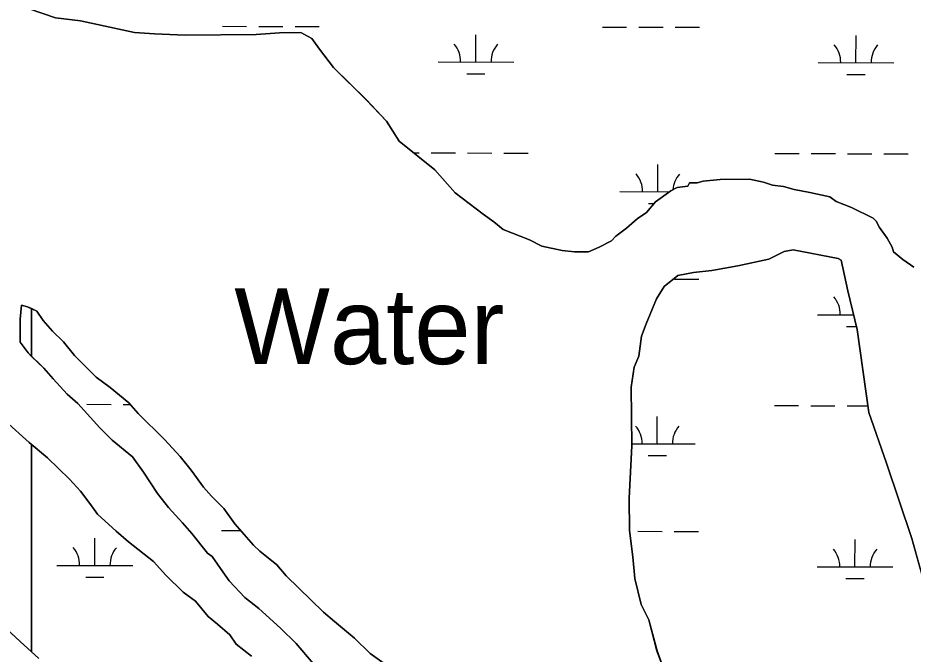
# Model space of a CAD drawing. Extents: x 3192952 to 3230831, y 849296 to 874698.
# Drawn here: x 3214925 to 3216108, y 863705 to 864544 of the extents above; entities that cross this region are included whole.
import ezdxf

# ---------------------------------------------------------------- set-up
doc = ezdxf.new("R2010")
doc.units = 0
for name, color, linetype in [('V-RIVR-IDEN', 7, 'Continuous'), ('V-SITE-VEGE', 7, 'Continuous'), ('V-TOPO-SHOR', 7, 'Continuous'), ('V-WETL-SWMP', 7, 'Continuous')]:
    doc.layers.add(name, color=color, linetype=linetype)

msp = doc.modelspace()

# ---------------------------------------------------------------- linework, layer by layer
at = {"layer": 'V-SITE-VEGE'}
for p, q in [((3214940.5, 864556), (3214975.3, 864544.2)), ((3214975.3, 864544.2), (3215007.9, 864540.4)), ((3215007.9, 864540.4), (3215079.3, 864524.8)), ((3215079.3, 864524.8), (3215105.8, 864523.1)), ((3215105.8, 864523.1), (3215146.5, 864521.4)), ((3215146.5, 864521.4), (3215240.1, 864522.3)), ((3215240.1, 864522.3), (3215270.7, 864524.7)), ((3215270.7, 864524.7), (3215299.2, 864525)), ((3215299.2, 864525), (3215313.5, 864517)), ((3215313.5, 864517), (3215323.8, 864502.8)), ((3215323.8, 864502.8), (3215342.4, 864478.6)), ((3215342.4, 864478.6), (3215385.5, 864436.2)), ((3215385.5, 864436.2), (3215412.3, 864408)), ((3215412.3, 864408), (3215428.8, 864381.7)), ((3215428.8, 864381.7), (3215476, 864343.5)), ((3215476, 864343.5), (3215502.8, 864313.2)), ((3215810.1, 864322.3), (3215812.1, 864326.4)), ((3215812.1, 864326.4), (3215822.3, 864326.5)), ((3215822.3, 864326.5), (3215830.4, 864328.6)), ((3215830.4, 864328.6), (3215852.8, 864330.9)), ((3215852.8, 864330.9), (3215891.5, 864331.3)), ((3215891.5, 864331.3), (3215909.8, 864327.4)), ((3215909.8, 864327.4), (3215922.1, 864323.4)), ((3215767.6, 864301.6), (3215787.8, 864316)), ((3215787.8, 864316), (3215795.9, 864320.2)), ((3215795.9, 864320.2), (3215810.1, 864322.3)), ((3215922.1, 864323.4), (3215936.4, 864321.5)), ((3215936.4, 864321.5), (3215950.7, 864317.6)), ((3215950.7, 864317.6), (3215971.1, 864313.7)), ((3215971.1, 864313.7), (3215997.6, 864307.9)), ((3215502.8, 864313.2), (3215539.7, 864285.1)), ((3215997.6, 864307.9), (3216005.8, 864301.9)), ((3215755.5, 864287.2), (3215767.6, 864301.6)), ((3216005.8, 864301.9), (3216026.2, 864293.9)), ((3216026.2, 864293.9), (3216054.9, 864280)), ((3215539.7, 864285.1), (3215554.1, 864275)), ((3215729.2, 864266.6), (3215743.4, 864278.9)), ((3215743.4, 864278.9), (3215755.5, 864287.2)), ((3216054.9, 864280), (3216059, 864275.9)), ((3215554.1, 864275), (3215566.4, 864265)), ((3215715.1, 864256.3), (3215729.2, 864266.6)), ((3216059, 864275.9), (3216063.1, 864267.8)), ((3216063.1, 864267.8), (3216073.4, 864253.7)), ((3215566.4, 864265), (3215601.1, 864251.1)), ((3215709.1, 864250.1), (3215715.1, 864256.3)), ((3215601.1, 864251.1), (3215617.5, 864243.1)), ((3215617.5, 864243.1), (3215644, 864237.2)), ((3215692.8, 864241.8), (3215709.1, 864250.1)), ((3216073.4, 864253.7), (3216079.7, 864241.5)), ((3215644, 864237.2), (3215660.3, 864235.4)), ((3215660.3, 864235.4), (3215678.7, 864235.5)), ((3215678.7, 864235.5), (3215692.8, 864241.8)), ((3215937.2, 864236), (3215917, 864225.7)), ((3215949.4, 864238.2), (3215937.2, 864236)), ((3216008.6, 864226.6), (3215949.4, 864238.2)), ((3216079.7, 864241.5), (3216081.8, 864235.4)), ((3216081.8, 864235.4), (3216094.1, 864225.4)), ((3215917, 864225.7), (3215876.3, 864217.1)), ((3216012.7, 864224.6), (3216008.6, 864226.6)), ((3216021.2, 864183.9), (3216012.7, 864224.6)), ((3216094.1, 864225.4), (3216108.4, 864215.3)), ((3215817.4, 864208.4), (3215797, 864204.1)), ((3215841.8, 864210.7), (3215817.4, 864208.4)), ((3215876.3, 864217.1), (3215841.8, 864210.7)), ((3215797, 864204.1), (3215778.9, 864189.7)), ((3215778.9, 864189.7), (3215768.8, 864173.3)), ((3216033.9, 864133.2), (3216021.2, 864183.9)), ((3215768.8, 864173.3), (3215754.9, 864140.6)), ((3215754.9, 864140.6), (3215749, 864124.3)), ((3216049.2, 864023.4), (3216033.9, 864133.2)), ((3215749, 864124.3), (3215745.2, 864097.7)), ((3215745.2, 864097.7), (3215739.2, 864083.4)), ((3215739.2, 864083.4), (3215735.4, 864056.9)), ((3215735.4, 864056.9), (3215736.1, 863979.6)), ((3216072.3, 863956.4), (3216049.2, 864023.4)), ((3215736.1, 863979.6), (3215732.8, 863910.3)), ((3216105.9, 863857), (3216072.3, 863956.4)), ((3215732.8, 863910.3), (3215733.2, 863867.6)), ((3215733.2, 863867.6), (3215737.6, 863833)), ((3216146, 863712.8), (3216105.9, 863857)), ((3215737.6, 863833), (3215739.9, 863804.5)), ((3215739.9, 863804.5), (3215748.4, 863770)), ((3215748.4, 863770), (3215758.8, 863749.7)), ((3215758.8, 863749.7), (3215769.3, 863709.1)), ((3215769.3, 863709.1), (3215781.9, 863674.6))]:
    msp.add_line(p, q, dxfattribs=at)
for points in [[(3215421.5, 863683.3), (3215390.7, 863705.4), (3215370.1, 863725.6), (3215343.5, 863747.7), (3215329.1, 863759.8), (3215279.8, 863808.1), (3215267.4, 863822.3), (3215244.8, 863840.4), (3215236.6, 863848.4), (3215211.9, 863876.7), (3215197.4, 863896.9), (3215181, 863913), (3215170.7, 863925.1), (3215154.2, 863947.4), (3215139.8, 863965.6), (3215119.2, 863987.7), (3215084.2, 864022), (3215071.9, 864036.1), (3215047.3, 864056.3), (3215028.8, 864070.3), (3215000, 864098.5), (3214985.6, 864116.7), (3214971.2, 864130.8), (3214958.8, 864145), (3214950.6, 864157.1), (3214938.3, 864163.1), (3214930.1, 864165), (3214928.3, 864146.7), (3214928.6, 864116.2), (3214938.9, 864102), (3214959.5, 864081.9), (3214971.8, 864067.7), (3214990.3, 864047.6), (3215004.7, 864035.5), (3215033.5, 864003.2), (3215050, 863987.1), (3215076.7, 863964.9)], [(3215234, 863701.8), (3215213.5, 863717.9), (3215205.2, 863730), (3215188.8, 863744.1), (3215176.5, 863754.2), (3215160, 863774.4), (3215143.6, 863786.4), (3215120.9, 863808.6), (3215104.5, 863826.8), (3215071.6, 863852.9), (3215055.2, 863867), (3215030.6, 863889.2), (3215020.3, 863903.3), (3215007.9, 863919.5), (3214993.5, 863935.6), (3214964.7, 863963.8), (3214940.1, 863983.9), (3214909.2, 864012.1)], [(3215076.7, 863964.9), (3215091.1, 863944.7), (3215109.7, 863916.4), (3215124.1, 863898.2), (3215142.7, 863878), (3215155, 863863.9), (3215175.6, 863837.6), (3215181.8, 863833.6), (3215196.2, 863813.4), (3215204.5, 863801.3), (3215225.1, 863779.1), (3215243.5, 863765), (3215272.3, 863738.8), (3215292.8, 863718.7), (3215315.5, 863692.4)], [(3214897.6, 863749.4), (3214928.4, 863721.2), (3214953, 863699)]]:
    msp.add_lwpolyline(points, dxfattribs=at)
at = {"layer": 'V-TOPO-SHOR'}
for points in [[(3216108.4, 864215.3), (3216094.1, 864225.4), (3216081.8, 864235.4), (3216079.7, 864241.5), (3216073.4, 864253.7), (3216063.1, 864267.8), (3216059, 864275.9), (3216054.9, 864280), (3216026.2, 864293.9), (3216005.8, 864301.9), (3215997.6, 864307.9), (3215971.1, 864313.7), (3215950.7, 864317.6), (3215936.4, 864321.5), (3215922.1, 864323.4), (3215909.8, 864327.4), (3215891.5, 864331.3), (3215852.8, 864330.9), (3215830.4, 864328.6), (3215822.3, 864326.5), (3215812.1, 864326.4), (3215810.1, 864322.3), (3215795.9, 864320.2), (3215787.8, 864316), (3215767.6, 864301.6), (3215755.5, 864287.2), (3215743.4, 864278.9), (3215729.2, 864266.6), (3215715.1, 864256.3), (3215709.1, 864250.1), (3215692.8, 864241.8), (3215678.7, 864235.5), (3215660.3, 864235.4), (3215644, 864237.2), (3215617.5, 864243.1), (3215601.1, 864251.1), (3215566.4, 864265), (3215554.1, 864275), (3215539.7, 864285.1), (3215502.8, 864313.2), (3215476, 864343.5), (3215428.8, 864381.7), (3215412.3, 864408), (3215385.5, 864436.2), (3215342.4, 864478.6), (3215323.8, 864502.8), (3215313.5, 864517), (3215299.2, 864525), (3215270.7, 864524.7), (3215240.1, 864522.3), (3215146.5, 864521.4), (3215105.8, 864523.1), (3215079.3, 864524.8), (3215007.9, 864540.4), (3214975.3, 864544.2), (3214940.5, 864556)], [(3215781.9, 863674.6), (3215769.3, 863709.1), (3215758.8, 863749.7), (3215748.4, 863770), (3215739.9, 863804.5), (3215737.6, 863833), (3215733.2, 863867.6), (3215732.8, 863910.3), (3215736.1, 863979.6), (3215735.4, 864056.9), (3215739.2, 864083.4), (3215745.2, 864097.7), (3215749, 864124.3), (3215754.9, 864140.6), (3215768.8, 864173.3), (3215778.9, 864189.7), (3215797, 864204.1), (3215817.4, 864208.4), (3215841.8, 864210.7), (3215876.3, 864217.1), (3215917, 864225.7), (3215937.2, 864236), (3215949.4, 864238.2), (3216008.6, 864226.6), (3216012.7, 864224.6), (3216021.2, 864183.9), (3216033.9, 864133.2), (3216049.2, 864023.4), (3216072.3, 863956.4), (3216105.9, 863857), (3216146, 863712.8)], [(3215315.5, 863692.4), (3215292.8, 863718.7), (3215272.3, 863738.8), (3215243.5, 863765), (3215225.1, 863779.1), (3215204.5, 863801.3), (3215196.2, 863813.4), (3215181.8, 863833.6), (3215175.6, 863837.6), (3215155, 863863.9), (3215142.7, 863878), (3215124.1, 863898.2), (3215109.7, 863916.4), (3215091.1, 863944.7), (3215076.7, 863964.9), (3215050, 863987.1), (3215033.5, 864003.2), (3215004.7, 864035.5), (3214990.3, 864047.6), (3214971.8, 864067.7), (3214959.5, 864081.9), (3214938.9, 864102), (3214928.6, 864116.2), (3214928.3, 864146.7), (3214930.1, 864165), (3214938.3, 864163.1), (3214950.6, 864157.1), (3214958.8, 864145), (3214971.2, 864130.8), (3214985.6, 864116.7), (3215000, 864098.5), (3215028.8, 864070.3), (3215047.3, 864056.3), (3215071.9, 864036.1), (3215084.2, 864022), (3215119.2, 863987.7), (3215139.8, 863965.6), (3215154.2, 863947.4), (3215170.7, 863925.1), (3215181, 863913), (3215197.4, 863896.9), (3215211.9, 863876.7), (3215236.6, 863848.4), (3215244.8, 863840.4), (3215267.4, 863822.3), (3215279.8, 863808.1), (3215329.1, 863759.8), (3215343.5, 863747.7), (3215370.1, 863725.6), (3215390.7, 863705.4), (3215421.5, 863683.3)], [(3214909.2, 864012.1), (3214940.1, 863983.9), (3214964.7, 863963.8), (3214993.5, 863935.6), (3215007.9, 863919.5), (3215020.3, 863903.3), (3215030.6, 863889.2), (3215055.2, 863867), (3215071.6, 863852.9), (3215104.5, 863826.8), (3215120.9, 863808.6), (3215143.6, 863786.4), (3215160, 863774.4), (3215176.5, 863754.2), (3215188.8, 863744.1), (3215205.2, 863730), (3215213.5, 863717.9), (3215234, 863701.8)], [(3214953, 863699), (3214928.4, 863721.2), (3214897.6, 863749.4)]]:
    msp.add_lwpolyline(points, dxfattribs=at)
at = {"layer": 'V-WETL-SWMP'}
for p, q in [((3214975.3, 864544.2), (3215007.9, 864540.4)), ((3215007.9, 864540.4), (3215079.3, 864524.8)), ((3215195.4, 864533.1), (3215227.4, 864533)), ((3215243.4, 864533), (3215275.4, 864532.9)), ((3215291.4, 864532.9), (3215323.4, 864532.8)), ((3215697.3, 864532.1), (3215729.3, 864532.1)), ((3215745.3, 864532.1), (3215777.3, 864532)), ((3215793.3, 864532), (3215825.3, 864531.9)), ((3215079.3, 864524.8), (3215105.8, 864523.1)), ((3215105.8, 864523.1), (3215146.5, 864521.4)), ((3215146.5, 864521.4), (3215240.2, 864522.4)), ((3215240.2, 864522.4), (3215270.7, 864524.7)), ((3215270.7, 864524.7), (3215299.2, 864525)), ((3215299.2, 864525), (3215313.5, 864517)), ((3215313.5, 864517), (3215323.8, 864502.8)), ((3215530.2, 864486), (3215530.2, 864522)), ((3216032.1, 864485.1), (3216032.2, 864521.1)), ((3215323.8, 864502.8), (3215342.4, 864478.6)), ((3215480.2, 864486.1), (3215580.2, 864485.9)), ((3215982.1, 864485.2), (3216082.1, 864485)), ((3215342.4, 864478.6), (3215385.6, 864436.2)), ((3215518.1, 864470.6), (3215542.1, 864470.6)), ((3216020.1, 864469.7), (3216044.1, 864469.6)), ((3215385.6, 864436.2), (3215412.3, 864408)), ((3215412.3, 864408), (3215428.8, 864381.7)), ((3215428.8, 864381.7), (3215476, 864343.5)), ((3215448.1, 864366.1), (3215455.1, 864366.1)), ((3215471.1, 864366.1), (3215503.1, 864366)), ((3215519.1, 864366), (3215551.1, 864365.9)), ((3215567.1, 864365.9), (3215599.1, 864365.8)), ((3215925, 864365.2), (3215957, 864365.1)), ((3215973, 864365.1), (3216005, 864365.1)), ((3216021, 864365), (3216053, 864365)), ((3216069, 864364.9), (3216101, 864364.9)), ((3215770.3, 864314.8), (3215770.4, 864350.8)), ((3215476, 864343.5), (3215502.8, 864313.2)), ((3215810.1, 864322.3), (3215812.1, 864326.4)), ((3215812.1, 864326.4), (3215822.3, 864326.5)), ((3215822.3, 864326.5), (3215830.4, 864328.6)), ((3215830.4, 864328.6), (3215852.8, 864330.9)), ((3215852.8, 864330.9), (3215891.5, 864331.3)), ((3215891.5, 864331.3), (3215909.9, 864327.4)), ((3215909.9, 864327.4), (3215922.1, 864323.4)), ((3215720.3, 864314.9), (3215786, 864314.7)), ((3215767.6, 864301.6), (3215787.8, 864316)), ((3215787.8, 864316), (3215795.9, 864320.2)), ((3215795.9, 864320.2), (3215810.1, 864322.3)), ((3215922.1, 864323.4), (3215936.4, 864321.5)), ((3215936.4, 864321.5), (3215950.7, 864317.6)), ((3215950.7, 864317.6), (3215971.1, 864313.7)), ((3215971.1, 864313.7), (3215997.6, 864307.9)), ((3215502.8, 864313.2), (3215539.7, 864285.1)), ((3215997.6, 864307.9), (3216005.8, 864301.9)), ((3215755.5, 864287.2), (3215767.6, 864301.6)), ((3215758.3, 864299.4), (3215765.7, 864299.3)), ((3216005.8, 864301.9), (3216026.2, 864293.9)), ((3216026.2, 864293.9), (3216054.9, 864280)), ((3215539.7, 864285.1), (3215554.1, 864275)), ((3215729.3, 864266.6), (3215743.4, 864278.9)), ((3215743.4, 864278.9), (3215755.5, 864287.2)), ((3216054.9, 864280), (3216059, 864275.9)), ((3215554.1, 864275), (3215566.4, 864265)), ((3215715.1, 864256.3), (3215729.3, 864266.6)), ((3216059, 864275.9), (3216063.1, 864267.8)), ((3216063.1, 864267.8), (3216073.5, 864253.7)), ((3215566.4, 864265), (3215601.1, 864251.1)), ((3215709.1, 864250.1), (3215715.1, 864256.3)), ((3215601.1, 864251.1), (3215617.5, 864243.1)), ((3215617.5, 864243.1), (3215644, 864237.2)), ((3215692.9, 864241.8), (3215709.1, 864250.1)), ((3216073.5, 864253.7), (3216079.7, 864241.5)), ((3215644, 864237.2), (3215660.3, 864235.4)), ((3215660.3, 864235.4), (3215678.7, 864235.5)), ((3215678.7, 864235.5), (3215692.9, 864241.8)), ((3215937.2, 864236), (3215917, 864225.7)), ((3215949.4, 864238.2), (3215937.2, 864236)), ((3216008.6, 864226.6), (3215949.4, 864238.2)), ((3216079.7, 864241.5), (3216081.8, 864235.4)), ((3216081.8, 864235.4), (3216094.1, 864225.4)), ((3215917, 864225.7), (3215876.3, 864217.1)), ((3216012.7, 864224.6), (3216008.6, 864226.6)), ((3216021.2, 864183.9), (3216012.7, 864224.6)), ((3216094.1, 864225.4), (3216108.4, 864215.3)), ((3215817.4, 864208.4), (3215797.1, 864204.1)), ((3215841.8, 864210.7), (3215817.4, 864208.4)), ((3215876.3, 864217.1), (3215841.8, 864210.7)), ((3215797.1, 864204.1), (3215778.9, 864189.7)), ((3215792.7, 864199.3), (3215824.7, 864199.2)), ((3215778.9, 864189.7), (3215768.9, 864173.3)), ((3216033.9, 864133.2), (3216021.2, 864183.9)), ((3215768.9, 864173.3), (3215754.9, 864140.6)), ((3215981.5, 864152.5), (3216029.1, 864152.4)), ((3215754.9, 864140.6), (3215749, 864124.3)), ((3216019.4, 864137), (3216033, 864137)), ((3216049.3, 864023.4), (3216033.9, 864133.2)), ((3215749, 864124.3), (3215745.2, 864097.7)), ((3215745.2, 864097.7), (3215739.2, 864083.4)), ((3215739.2, 864083.4), (3215735.4, 864056.9)), ((3215735.4, 864056.9), (3215736.2, 863979.6)), ((3215016.6, 864034.3), (3215048.6, 864034.2)), ((3215064.6, 864034.2), (3215073.6, 864034.1)), ((3215924.4, 864032.5), (3215956.4, 864032.5)), ((3215972.4, 864032.4), (3216004.4, 864032.4)), ((3216020.4, 864032.4), (3216048, 864032.3)), ((3216072.3, 863956.4), (3216049.3, 864023.4)), ((3214940.1, 863983.9), (3214909.2, 864012.1)), ((3215769.7, 863982.1), (3215769.8, 864018.1)), ((3214943.5, 863981.1), (3214940.1, 863983.9)), ((3214943.5, 863707.6), (3214943.5, 863981.1)), ((3215736.2, 863979.6), (3215732.8, 863910.3)), ((3215736.1, 863982.1), (3215819.7, 863982)), ((3215757.7, 863966.7), (3215781.7, 863966.6)), ((3216105.9, 863857), (3216072.3, 863956.4)), ((3215732.8, 863910.3), (3215733.2, 863867.6)), ((3215194.2, 863867.7), (3215219.8, 863867.7)), ((3215733.2, 863867.6), (3215737.6, 863833)), ((3215744.1, 863866.7), (3215776.1, 863866.6)), ((3215792.1, 863866.6), (3215824.1, 863866.6)), ((3215027, 863821.6), (3215027.1, 863857.6)), ((3216030.8, 863819.7), (3216030.9, 863855.7)), ((3216146, 863712.8), (3216105.9, 863857)), ((3215737.6, 863833), (3215739.9, 863804.5)), ((3214977, 863821.7), (3215077, 863821.5)), ((3215980.8, 863819.8), (3216080.8, 863819.6)), ((3215015, 863806.2), (3215039, 863806.2)), ((3215739.9, 863804.5), (3215748.4, 863770)), ((3216018.8, 863804.3), (3216042.8, 863804.3)), ((3215748.4, 863770), (3215758.8, 863749.7)), ((3214897.6, 863749.4), (3214928.4, 863721.2)), ((3215758.8, 863749.7), (3215769.4, 863709.1)), ((3214928.4, 863721.2), (3214943.5, 863707.6)), ((3215769.4, 863709.1), (3215781.9, 863674.6))]:
    msp.add_line(p, q, dxfattribs=at)
msp.add_lwpolyline([(3214943.5, 864160.5), (3214938.3, 864163.1), (3214930.1, 864165), (3214928.3, 864146.7), (3214928.6, 864116.2), (3214938.9, 864102), (3214943.5, 864097.5)], close=True, dxfattribs=at)
for points in [[(3215421.5, 863683.3), (3215390.7, 863705.4), (3215370.1, 863725.6), (3215343.5, 863747.7), (3215329.1, 863759.8), (3215279.8, 863808.1), (3215267.4, 863822.3), (3215244.8, 863840.4), (3215236.6, 863848.4), (3215211.9, 863876.7), (3215197.4, 863896.9), (3215181, 863913), (3215170.7, 863925.1), (3215154.2, 863947.4), (3215139.8, 863965.6), (3215119.2, 863987.7), (3215084.2, 864022), (3215071.9, 864036.1), (3215047.3, 864056.3), (3215028.8, 864070.3), (3215000, 864098.5), (3214985.6, 864116.7), (3214971.2, 864130.8), (3214958.8, 864145), (3214950.6, 864157.1), (3214943.5, 864160.5), (3214943.5, 864097.5), (3214959.5, 864081.9), (3214971.8, 864067.7), (3214990.3, 864047.6), (3215004.7, 864035.5), (3215033.5, 864003.2), (3215050, 863987.1), (3215076.7, 863964.9), (3215091.1, 863944.7), (3215109.7, 863916.4), (3215124.1, 863898.2), (3215142.7, 863878), (3215155, 863863.9), (3215175.6, 863837.6), (3215181.8, 863833.6), (3215196.2, 863813.4)], [(3215234, 863701.8), (3215213.5, 863717.9), (3215205.2, 863730), (3215188.8, 863744.1), (3215176.5, 863754.2), (3215160, 863774.4), (3215143.6, 863786.4), (3215120.9, 863808.6), (3215104.5, 863826.8), (3215071.6, 863852.9), (3215055.2, 863867), (3215030.6, 863889.2), (3215020.3, 863903.3), (3215007.9, 863919.5), (3214993.5, 863935.6), (3214964.7, 863963.8), (3214943.5, 863981.1), (3214943.5, 863707.6)], [(3215196.2, 863813.4), (3215204.5, 863801.3), (3215225.1, 863779.1), (3215243.5, 863765), (3215272.3, 863738.8), (3215292.9, 863718.7), (3215315.5, 863692.4)], [(3214943.5, 863707.6), (3214953, 863699)]]:
    msp.add_lwpolyline(points, dxfattribs=at)
for centre, start, end in [((3215474.9, 864486.6), 359.1198, 40.6635), ((3215585.4, 864486.4), 139.1198, 180.6635), ((3215976.8, 864485.7), 359.1198, 40.6635), ((3216087.3, 864485.4), 139.1198, 180.6635), ((3215715.1, 864315.3), 359.1198, 40.6635), ((3215825.6, 864315.1), 139.1198, 176.4178), ((3215976.2, 864153), 359.1198, 40.6635), ((3215714.5, 863982.7), 359.1198, 40.6635), ((3215824.9, 863982.5), 139.1198, 180.6635), ((3214971.8, 863822.2), 359.1198, 40.6635), ((3215082.2, 863822), 139.1198, 180.6635), ((3215975.6, 863820.3), 359.1198, 40.6635), ((3216086.1, 863820.1), 139.1198, 180.6635)]:
    msp.add_arc(centre, 35.2, start, end, dxfattribs=at)

# ---------------------------------------------------------------- texts
at = {"layer": 'V-RIVR-IDEN'}
msp.add_text('Water', height=100, dxfattribs=at).set_placement((3215211.2, 864087.3))

doc.saveas('drawing.dxf')
